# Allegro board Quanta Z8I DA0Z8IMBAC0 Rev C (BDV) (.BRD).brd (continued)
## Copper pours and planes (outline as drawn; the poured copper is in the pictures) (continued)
+USBPWRD2 on BOTTOM (solid shape): 229.19,125.3 229.19,124.81 227.9,124.81 227.9,124.61 229.19,124.61 229.19,124.31 227.9,124.31 227.9,124.11 229.19,124.11 229.19,123.81 227.9,123.81 227.9,123.61 229.19,123.61 229.19,123.34 229.17,123.31 226.75,123.31 226.61,123.45 226.61,125.11 226.82,125.31 229.18,125.31
+USBPWRD2 on BOTTOM (solid shape): 221.12,106.73 221.12,105.23 221,105.12 220.6,105.12 220.39,104.92 220.39,104.05 220.03,103.69 220,103.69 219.78,103.63 219.63,103.47 219.62,103.44 218.15,103.44 217.86,103.73 217.86,105.26 218.01,105.41 218.01,106.76 218.06,106.81 221.04,106.81
+USBPWRD2 on BOTTOM (solid shape): 212.45,114.58 212.45,111.99 211.89,111.43 210.52,111.43 210.3,111.65 210.3,112.88 211.8,112.88 211.8,113.71 211.6,113.71 211.6,112.88 211.3,112.88 211.3,113.71 211.1,113.71 211.1,112.88 210.8,112.88 210.8,113.71 210.6,113.71 210.6,112.88 210.3,112.88 210.3,114.51 210.62,114.83 212.2,114.83
+USBPWRD2 on IN3 (solid shape): outline of 1535 points within 210.32,103.49 230.23,125.45
+VAC_IN on TOP (solid shape): 14.02,198.93 14.02,196.6 14.5,196.13 14.99,196.13 15.23,195.89 15.23,193.9 14.84,193.51 13.27,193.51 11.51,195.28 11.51,197.28 10.67,198.12 9.68,198.12 9.22,198.57 9.22,199.64 9.86,200.28 12.68,200.28
+VAC_IN on TOP (solid shape): 57.13,201.8 57.13,200.73 57.33,200.53 61.01,200.53 61.22,200.33 61.22,197.46 61.15,197.34 61.13,197.2 61.13,197.13 61.15,197.05 61.17,197.02 59.67,195.53 56.72,195.53 56.5,195.75 56.5,196.06 56.49,196.1 56.49,197.2 55.82,197.88 55.82,198.56 55.96,198.7 55.96,201.95 56.09,202.08 56.85,202.08
+VAC_IN on SVCC (solid shape): outline of 96 points within 7.27,190.04 62.28,210.67
+VAC_IN on IN2 (solid shape): outline of 971 points within 9.58,191.08 62.24,202.25
+VAC_IN on IN4 (solid shape): outline of 961 points within 9.4,191.11 62.28,201.99
+VGPU_CORE on TOP (solid shape): 130.03,191.42 130.29,191.15 130.3,191.15 130.38,191.05 130.51,191.01 130.61,191.01 130.69,190.97 130.71,190.89 130.71,190.85 130.78,190.64 130.97,190.51 130.98,190.51 131.11,190.37 131.11,190.29 131.1,190.26 131.06,190.24 131,190.18 131,190.07 130.89,189.96 130.41,189.96 129.61,190.76 129.6,190.8 129.61,190.83 129.81,191.03 129.81,191.03 129.91,191.11 129.94,191.24 129.94,191.38 129.96,191.41 129.99,191.43
+VGPU_CORE on TOP (solid shape): 113.41,215.97 113.44,215.9 113.4,215.82 112.3,214.4 111.9,212.65 112.61,210.34 114.5,208.83 114.5,204.74 113.89,204.13 113.87,204.13 113.68,204.04 113.55,203.86 113.53,203.83 112.08,203.83 111.77,203.52 111.77,202.52 111.95,202.34 112.13,202.34 112.37,202.1 112.37,200.99 112.26,200.89 108.72,200.89 106.83,202.78 106.8,202.78 106.75,202.82 106.68,202.83 105.99,202.83 105.57,203.26 105.57,204.13 106.39,204.95 106.39,206.93 104.31,209.01 104.31,210.94 106.39,213.02 106.39,213.31 109.91,216.84 110.22,216.84 110.52,217.14 112.24,217.14
+VGPU_CORE on TOP (solid shape): outline of 2141 points within 124.36,190.24 136.43,209.57
+VGPU_CORE on BOTTOM (solid shape): 112.45,216.79 112.45,214.69 112.44,214.68 112.04,213.7 111.9,212.65 112.04,211.6 112.44,210.62 112.45,210.61 112.45,210.21 113.29,209.37 113.29,206.35 113.66,205.98 113.98,205.98 114.21,205.75 114.21,204.84 113.29,203.92 113.29,201.57 112.42,200.71 108.51,200.71 107.7,201.52 107.7,208.02 105.54,210.18 105.54,210.41 109.85,214.72 109.85,214.85 109.85,214.86 109.85,215.22 109.85,215.23 109.85,216.34 110.66,217.16 112.08,217.16
+VGPU_CORE on BOTTOM (solid shape): outline of 623 points within 129.9,204.36 141.58,217.42
+VGPU_CORE on SVCC (solid shape): 140.15,217.47 140.06,217.34 140.03,217.2 140.1,216.99 140.26,216.85 140.26,209.14 140.18,209.02 140.15,208.87 140.18,208.73 140.26,208.6 140.26,206.88 135.76,202.39 135.71,202.3 135.69,202.21 135.69,202.13 135.58,202.01 135.54,201.85 135.58,201.69 135.69,201.56 135.69,199.6 135.59,199.48 135.56,199.33 135.59,199.18 135.69,199.05 135.69,192.93 135.59,192.81 135.56,192.65 135.59,192.5 135.69,192.38 135.69,188.85 134.57,187.73 133.18,187.73 133.05,187.91 132.84,187.98 132.63,187.91 132.5,187.73 126.4,187.73 123.81,190.31 123.72,190.5 123.53,190.6 116.86,197.27 116.88,197.35 116.89,197.44 116.78,197.71 116.51,197.82 116.43,197.81 116.35,197.78 115.8,198.32 115.72,198.38 115.62,198.4 110.9,198.4 104.45,204.85 104.45,211.37 110.54,217.47
+VGPU_CORE on IN2 (solid shape): outline of 6717 points within 104.58,188.21 140.15,217.44
+VGPU_CORE on IN3 (solid shape): outline of 2725 points within 124.54,190.11 134.86,206.8
+VGPU_CORE on IN4 (solid shape): outline of 4682 points within 125.22,189.04 143.94,217.47
ADOGND on TOP (solid shape): outline of 506 points within 10.57,24.72 23.58,38.56
ADOGND on TOP (solid shape): outline of 644 points within 1.01,14.81 23.45,29.83
ADOGND on BOTTOM (solid shape): 13.08,24.83 13.08,24.58 13.13,24.53 13.13,19.7 13.6,19.23 13.61,17.2 11.85,16.19 10.33,16.19 10.24,16.25 10.26,16.36 10.44,16.61 10.5,16.91 10.5,16.99 10.48,17.08 10.5,17.16 10.58,17.2 11.67,17.2 12.63,17.96 12.16,19.08 12.16,23.44 12.62,24.57 11.65,25.32 10.64,25.32 10.64,25.64 12.26,25.64
ADOGND on BOTTOM (solid shape): outline of 132 points within 12.73,14.81 23.53,28.42
ADOGND on SGND (solid shape): outline of 116 points within 1.01,14.35 23.55,38.58
ADOGND on IN1 (solid shape): 5.49,29.64 5.51,29.45 5.52,29.25 5.52,27.65 5.51,27.44 5.48,27.24 5.58,27.14 11.88,27.14 13.23,25.79 13.87,24.41 13.37,22.98 13.37,19.54 13.81,18.71 13.83,17.78 12.65,16.6 12.14,16.6 11.72,16.19 10.33,16.19 10.24,16.25 10.26,16.36 10.44,16.61 10.5,16.91 10.5,16.99 10.48,17.08 10.5,17.16 10.58,17.2 11.67,17.2 12.63,17.96 12.16,19.08 12.16,23.44 12.62,24.57 11.65,25.32 10.18,25.32 10.1,25.36 10.08,25.44 10.1,25.53 10.1,25.61 10.04,25.91 9.86,26.16 9.66,26.36 6,26.36 5.69,26.06 5.62,26.03 5.55,26.05 5.37,26.17 5.15,26.21 4.39,26.21 3.97,26.03 3.79,25.61 3.8,25.53 3.81,25.45 3.8,25.36 3.72,25.32 2.67,25.32 2.73,25.46 2.75,25.61 2.57,26.03 2.15,26.21 1.39,26.21 1.19,26.17 1.01,26.07 1.01,26.64 3.5,26.64 4.21,26.94 4.51,27.65 4.51,29.25 4.5,29.38 4.47,29.52 4.49,29.6 4.57,29.64
ADOGND on SVCC (solid shape): outline of 111 points within 3.43,14.35 23.55,38.58
ADOGND on IN2 (solid shape): outline of 1139 points within 1.01,14.96 23.53,38.56
ADOGND on IN3 (solid shape): 5.49,29.64 5.51,29.45 5.52,29.25 5.52,27.65 5.51,27.44 5.48,27.24 5.58,27.14 11.88,27.14 13.23,25.79 13.87,24.41 13.37,22.98 13.37,19.54 13.75,18.91 13.87,18.19 13.3,17.61 13.08,17.61 13.07,17.62 12.81,17.62 12.59,17.84 12.6,18.54 12.16,19.08 12.16,23.44 12.62,24.57 11.65,25.32 10.18,25.32 10.1,25.36 10.08,25.44 10.1,25.53 10.1,25.61 10.04,25.91 9.86,26.16 9.66,26.36 6.25,26.36 5.92,26.03 5.61,26.03 5.4,26.18 5.15,26.23 4.39,26.23 3.95,26.05 3.77,25.61 3.78,25.48 3.82,25.35 3.84,25.32 2.7,25.32 2.76,25.46 2.77,25.61 2.59,26.05 2.15,26.23 1.39,26.23 1.19,26.2 1.01,26.1 1.01,26.64 3.5,26.64 4.21,26.94 4.51,27.65 4.51,29.25 4.5,29.38 4.47,29.52 4.49,29.6 4.57,29.64
ADOGND on SGND1 (solid shape): outline of 115 points within 1.01,14.35 23.55,38.58
ADOGND on IN4 (solid shape): outline of 1031 points within 1.01,14.81 23.53,38.56
ADOGND on SGND2 (solid shape): outline of 118 points within 1.01,14.35 23.55,38.58
BAT-V on TOP (solid shape): outline of 1888 points within 101.4,94.54 138.48,117.01
BAT-V on BOTTOM (solid shape): 138.61,114.93 138.61,113.89 139.47,113.03 139.47,112.4 138.85,112.4 138.31,112.95 135.23,112.95 134.74,113.45 134.74,114.11 135.56,114.93 135.56,115.67 135.82,115.92 137.62,115.92
BAT-V on BOTTOM (solid shape): 101.95,105.55 101.95,104.67 102.59,104.02 102.59,102.29 102.77,102.12 103.93,102.12 104.06,101.99 104.06,100.69 103.58,100.22 100.57,100.22 100.1,100.68 100.1,101.62 99.39,102.33 99.39,104.36 100.01,104.97 100.16,105.13 100.16,105.71 100.26,105.81 101.69,105.81
CRT_VCC_R on TOP (solid shape): 17.79,150.05 17.79,149.13 17.7,149.04 16.8,149.04 16.33,148.57 13.64,148.57 13.58,148.64 13.58,149.41 14.39,150.22 17.62,150.22
CRT_VCC_R on TOP (solid shape): 26.89,157.94 26.89,156.52 27.28,156.13 27.69,156.13 28.62,155.2 28.62,153.98 27.8,153.98 27.64,154.13 27.64,154.89 26.32,156.21 25.92,156.21 25.82,156.31 25.82,157.12 25.42,157.52 25.42,158.33 25.56,158.46 26.37,158.46
CRT_VCC_R on BOTTOM (solid shape): 11.01,159.98 11.01,158.08 10.92,157.99 10.92,157.63 10.74,157.46 9.31,157.46 8.32,158.44 6.04,158.44 5.86,158.63 5.86,159.23 6.09,159.46 6.16,159.46 6.2,159.45 6.28,159.43 6.36,159.41 6.44,159.41 6.52,159.42 6.59,159.44 6.63,159.46 6.73,159.36 8.36,159.36 8.54,159.53 9.2,159.53 9.2,159.48 9.21,159.42 9.23,159.37 9.26,159.32 9.29,159.27 9.33,159.23 9.38,159.2 9.43,159.17 9.48,159.15 9.53,159.13 9.59,159.13 9.65,159.13 9.7,159.14 9.76,159.16 9.81,159.18 9.86,159.21 9.9,159.25 9.93,159.29 9.96,159.34 9.99,159.39 10,159.45 10.01,159.51 10.01,159.56 10,159.62 9.99,159.67 9.96,159.73 9.93,159.77 9.9,159.82 9.86,159.86 9.81,159.89 9.76,159.91 9.7,159.93 9.65,159.94 9.59,159.94 9.53,159.94 9.48,159.92 9.43,159.9 9.38,159.87 9.33,159.84 9.29,159.8 9.26,159.75 9.23,159.7 9.21,159.65 9.2,159.59 9.2,159.53 8.54,159.53 9.28,160.27 10.72,160.27
CRT_VCC_R on IN1 (solid shape): 15.61,150.11 16.74,150.11 17.09,149.76 17.09,148.92 16.82,148.64 15.62,148.64 15.61,148.63 14.31,148.63 14.13,148.81 14.13,149.08 14.14,149.09 14.14,149.72 14.66,150.24 15.48,150.24
CRT_VCC_R on IN1 (solid shape): 26.74,157.98 26.74,157.64 26.78,157.43 26.9,157.25 27.16,156.99 27.16,155.98 26.93,155.75 26.04,155.75 25.84,155.95 25.84,158.11 26.61,158.11
CRT_VCC_R on IN1 (solid shape): 10.85,158.09 10.85,157.41 10.94,157.32 10.97,157.24 10.94,157.17 10.86,157.06 10.83,156.92 10.92,156.68 11.19,156.54 11.2,156.51 11.2,155.71 11.1,155.61 9.16,155.61 8.97,155.8 8.94,155.88 8.99,155.96 9.11,156.09 9.15,156.26 9.05,156.51 8.8,156.62 8.76,156.63 8.74,156.67 8.74,158.14 8.94,158.34 10.6,158.34
EN_SA on TOP (solid shape): 167.31,130.71 167.25,130.64 167.25,129.36 167.21,129.32 166.84,129.32 166.37,129.79 166.37,131.01 167.31,131.01
FBA_VREFC_1 on BOTTOM (solid shape): 159.35,186.87 159.35,186.45 159.41,186.39 159.41,185.92 159.29,185.79 159.16,185.61 159.12,185.39 159.12,184.45 159.13,184.35 159.13,184.02 159.02,183.91 159.02,183.1 158.99,183.06 158.84,183.06 158.75,183.15 158.75,183.56 158.51,183.8 158.51,185.93 158.76,186.18 158.84,186.28 158.9,186.39 158.97,186.45 158.97,186.89 159.03,186.91 159.3,186.91
G5335-AGND-2 on TOP (solid shape): 169.71,157.13 169.71,155.82 169.67,155.72 169.65,155.61 169.66,155.51 169.7,155.42 169.71,155.39 169.67,155.35 169.67,153.66 169.61,153.6 169.61,152.79 168.3,152.79 168.11,152.97 168.11,153.39 167.91,153.59 167.91,153.88 168.02,154 168.27,154 168.34,153.98 168.4,153.98 168.66,154.07 168.8,154.31 168.8,154.33 168.81,154.34 168.81,156.91 169.19,157.29 169.55,157.29 169.55,157.29
G5335-AGND-2 on BOTTOM (solid shape): 168.71,153.46 168.71,152.86 168.63,152.78 168.26,152.78 168.19,152.85 168.19,153.24 168.18,153.29 168.17,153.37 168.14,153.39 168.11,153.43 167.68,153.86 167.64,153.9 167.5,154.03 167.42,154.03 167.42,154.04 166.63,154.04 166.63,154.29 167.42,154.29 167.42,154.29 167.66,154.29 167.66,154.29 167.88,154.29
G5335-LX-1 on BOTTOM (solid shape): 140.16,128.29 140.77,128.29 141.28,127.78 142.8,127.78 142.8,126.9 142.92,126.78 143.58,126.78 143.67,126.69 143.67,124.15 143.31,123.8 143.31,122.59 143.7,122.2 143.7,121.57 143.54,121.41 142.73,121.41 142.37,121.76 142.37,123 143.06,123 143.06,123.79 142.82,123.79 142.82,123 142.37,123 142.37,123.85 142.43,123.9 142.46,123.92 142.5,123.97 142.5,125.9 142.4,126.01 142.34,126.01 142.34,126.02 141.55,126.02 141.55,126.01 140.19,126.01 139.78,125.6 139.75,125.58 139.69,125.55 139.64,125.5 139.6,125.45 139.56,125.4 139.55,125.37 139.35,125.17 135.54,125.17 135.53,125.16 135.33,125.35 135.33,126.27 142.34,126.27 142.34,126.52 141.55,126.52 141.55,126.27 135.33,126.27 135.33,127.01 135.36,127.03 135.4,127.07 135.43,127.11 135.46,127.16 135.48,127.21 135.49,127.26 135.5,127.31 135.5,127.38 135.49,127.45 135.47,127.51 135.72,127.76 138.66,127.76 139.53,128.62 139.83,128.62
G5335-LX-2 on BOTTOM (solid shape): 164.5,160.64 164.5,159.6 163.77,158.86 163.77,157.79 163.46,157.48 163.46,157.1 163.74,156.82 163.89,156.82 163.9,156.8 163.9,156.02 163.9,155.81 164,155.71 164.63,155.71 164.63,153.16 164.4,152.93 164.4,152.03 164.15,152.03 164.15,152.81 163.9,152.81 163.9,152.03 163.65,152.03 163.65,153.04 163.72,153.11 163.72,154.75 163.44,155.04 162.65,155.04 162.4,155.29 163.42,155.29 163.42,155.54 162.63,155.54 162.63,155.29 162.4,155.29 159.62,158.07 159.62,158.09 158.86,158.85 158.84,158.85 158.28,159.41 158.28,160.65 158.68,161.05 164.1,161.05
G5719LX1.5V on BOTTOM (solid shape): 9.91,34.95 9.91,34.09 9.83,34.01 9.45,34.01 9.15,33.71 8.55,33.1 6.13,33.1 6.06,33.17 6.06,33.92 6.13,33.99 7.38,33.99 7.61,34.22 7.61,34.75 7.91,35.05 9.81,35.05
L_SPK+ on TOP (solid shape): 40.53,94.09 40.53,93.23 40.48,93.17 40.47,93.17 40.28,92.99 39.91,92.99 39.72,93.17 38.69,93.17 38.52,93.35 38.52,94.08 38.61,94.18 40.44,94.18
L_SPK+ on BOTTOM (solid shape): 19.55,37.63 19.55,36.74 19.51,36.7 19.51,35.01 19.51,35.01 19.32,35.01 19.31,35.02 19.31,36.49 19.06,36.74 19.06,37.64 19.17,37.75 19.43,37.75
L_SPK+ on IN4 (solid shape): 19.89,40.34 19.89,38.26 19.58,37.95 19.58,36.75 19.43,36.59 19.11,36.59 19.02,36.69 19.02,37.85 18.38,38.48 18.38,40.48 18.94,41.03 19.19,41.03
L_SPK+ on IN4 (solid shape): 39.35,94.69 39.48,94.52 39.68,94.45 39.7,94.45 39.85,94.48 39.98,94.58 40.04,94.59 40.09,94.56 40.21,94.48 40.34,94.45 40.42,94.45 40.47,94.47 40.55,94.44 40.58,94.37 40.58,93.77 40.44,93.64 37.98,93.64 37.92,93.69 37.92,94.67 37.99,94.73 39.33,94.73
L_SPK+_1 on TOP (solid shape): 38.37,92.87 39.51,92.87 39.64,92.74 39.64,91.78 39.6,91.74 37.85,91.74 37.17,92.42 37.17,93.07 37.25,93.15 38.09,93.15
L_SPK+_1 on TOP (solid shape): 42.42,101.57 42.42,100.68 42.31,100.58 42.31,100.05 42.21,99.94 41.41,99.94 41.28,100.08 41.28,101.36 41.14,101.49 41.14,101.76 41.32,101.94 42.05,101.94
L_SPK+_1 on BOTTOM (solid shape): 82.02,198.7 82.02,196.41 81.87,196.26 81,196.26 80.85,196.41 80.85,198.7 81.05,198.9 81.82,198.9
L_SPK+_1 on IN4 (solid shape): 82.02,197.51 82.02,196.41 81.87,196.26 81,196.26 80.85,196.41 80.85,197.63 80.98,197.76 81.77,197.76
L_SPK+_1 on IN4 (solid shape): 42.29,102.16 42.29,101.62 42.22,101.54 41.2,101.54 41.16,101.58 41.16,101.86 41.12,101.91 40.43,102.59 40.43,102.75 40.89,103.21 41.24,103.21
L_SPK+_2 on TOP (solid shape): 41.58,96.38 41.58,96.02 41.46,95.91 41.22,95.91 40.58,95.27 40.58,94.64 40.5,94.56 38.58,94.56 38.57,94.57 38.57,95.3 38.88,95.61 40.11,95.61 40.97,96.47 41.49,96.47
L_SPK+_2 on BOTTOM (solid shape): 39.49,98.48 39.49,96.62 40.58,95.53 40.58,94.67 40.46,94.56 39.31,94.56 38.62,95.25 38.62,96.52 38.72,96.62 38.72,98.45 38.77,98.5 39.47,98.5
L_SPK- on TOP (solid shape): 42.86,94.05 42.86,93.27 42.77,93.19 40.95,93.19 40.84,93.31 40.84,94.15 40.87,94.18 42.73,94.18
L_SPK- on BOTTOM (solid shape): 20.96,40.12 20.96,38.38 20.3,37.71 20.27,37.69 20.24,37.66 20.17,37.58 20.17,37.49 20.17,37.38 20.17,36.47 19.91,36.21 19.91,35.02 19.91,35.01 19.74,35.01 19.71,35.04 19.71,36 19.71,36.32 19.64,36.39 19.64,36.68 19.66,36.7 19.66,36.78 19.66,36.85 19.66,36.92 19.66,37.44 19.66,37.51 19.66,37.58 19.66,37.89 20.03,38.26 20.03,38.89 19.42,39.5 19.42,40.05 19.66,40.29 20.79,40.29
L_SPK- on IN4 (solid shape): 21.88,40.69 21.88,39.99 20.86,38.98 20.65,38.98 20.29,39.33 20.29,40.25 21.05,41 21.57,41
L_SPK- on IN4 (solid shape): 42.78,94.07 42.78,93.11 42.01,92.34 41.57,92.34 40.9,93.02 40.9,93.6 40.91,93.61 40.91,94.1 40.95,94.15 42.71,94.15
L_SPK-_1 on TOP (solid shape): 42.4,92.6 42.4,91.9 40.91,90.41 39.75,90.41 39.66,90.5 39.66,91.32 41.09,92.75 42.26,92.75
L_SPK-_1 on TOP (solid shape): 40.82,101.83 40.82,101.38 40.97,101.23 40.97,100.5 40.97,100.44 40.96,100.38 40.96,99.71 40.92,99.66 40,99.66 39.94,99.72 39.94,100.96 39.69,101.22 39.69,101.61 39.7,101.66 39.7,101.7 39.7,101.91 39.77,101.97 40.67,101.97
L_SPK-_1 on BOTTOM (solid shape): 83.52,198.75 83.52,196.47 83.37,196.31 82.5,196.31 82.35,196.47 82.35,198.75 82.55,198.95 83.32,198.95
L_SPK-_1 on IN4 (solid shape): 83.52,197.76 83.52,196.47 83.37,196.31 82.5,196.31 82.35,196.47 82.35,198.07 82.43,198.14 83.14,198.14
L_SPK-_1 on IN4 (solid shape): 40.05,102.54 40.49,102.1 40.81,101.78 40.81,101.63 40.73,101.54 39.51,101.54 38.58,102.47 38.58,102.63 39.24,103.29 39.3,103.29
L_SPK-_2 on TOP (solid shape): 43.26,95.95 43.26,95.42 42.88,95.03 42.88,94.62 42.82,94.56 40.82,94.56 40.76,94.63 40.76,94.76 40.77,94.8 40.76,94.84 40.75,94.9 41.35,95.49 42.2,95.49 42.72,96.01 43.2,96.01
L_SPK-_2 on BOTTOM (solid shape): 40.75,98.47 40.75,96.61 40.86,96.5 41.05,96.5 42.17,95.38 42.63,95.38 42.88,95.13 42.88,94.68 42.73,94.52 40.91,94.52 40.77,94.67 40.77,95.56 39.97,96.36 39.97,98.48 40,98.52 40.7,98.52
LGATE1_CORE on BOTTOM (solid shape): 149.84,156.56 149.84,156.13 149.99,155.98 150.96,155.98 150.96,155.37 149.3,155.37 149.3,156.56 149.41,156.66 149.74,156.66
MUX_3V on TOP (solid shape): 33.08,131.31 33.08,130.89 33.28,130.69 34.2,130.69 34.4,130.49 34.4,128.88 34.33,128.81 33.34,128.81 33.23,128.7 32.68,128.7 32.53,128.84 30.85,128.84 30.78,128.85 29.12,128.85 28.78,128.51 28.01,128.51 27.92,128.6 27.92,128.8 28.53,129.41 31.51,129.41 31.85,129.75 32.38,129.75 32.58,129.95 32.58,131.32 32.64,131.38 33.02,131.38
MUX_3V on BOTTOM (solid shape): outline of 1000 points within 19.27,119.04 34.64,133.82
Net_88 on TOP (solid shape): 8.44,48.63 4.63,48.63 4.59,48.68 4.59,51.23 8.44,51.23
Net_88 on BOTTOM (solid shape): 8.44,51.22 8.44,48.83 8.25,48.63 4.63,48.63 4.59,48.68 4.59,51.23 8.43,51.23
Net_88 on IN1 (solid shape): 8.44,48.63 4.63,48.63 4.59,48.68 4.59,51.23 8.44,51.23
Net_88 on IN2 (solid shape): 8.44,48.63 4.63,48.63 4.59,48.68 4.59,51.23 8.44,51.23
Net_88 on IN3 (solid shape): 8.44,48.63 4.63,48.63 4.59,48.68 4.59,51.23 8.44,51.23
Net_88 on IN4 (solid shape): 8.45,48.63 4.63,48.63 4.59,48.68 4.59,51.23 8.45,51.23
PHASE1_CORE on BOTTOM (solid shape): 148.69,156.36 148.69,155.24 148.91,155.03 149.22,155.03 149.23,155.01 149.66,155.01 149.7,154.97 149.7,154.97 149.98,154.68 149.98,151.59 149.97,151.58 146.87,151.58 146.69,151.76 146.69,154.32 146.8,154.32 146.9,154.37 146.95,154.48 146.95,154.86 146.9,154.97 146.8,155.01 146.69,155.01 146.69,156.38 146.89,156.59 148.47,156.59
PHASE2_CORE on BOTTOM (solid shape): 157,144.78 157,144.37 156.72,144.09 156.2,144.09 156.19,144.1 155.25,144.1 155.25,144.4 156.21,144.4 156.37,144.55 156.37,144.8 156.52,144.95 156.82,144.95
PHASE2_CORE on BOTTOM (solid shape): 151.64,139.52 151.64,136.09 151.36,135.81 149.62,135.81 149.61,135.81 149.35,135.55 149.34,135.55 149.22,135.46 149.14,135.34 149.13,135.33 149,135.2 148.54,135.2 148.34,135.4 148.34,137.53 148.37,137.55 148.44,137.6 148.46,137.69 148.46,138.07 148.44,138.15 148.37,138.21 148.34,138.22 148.34,139.7 151.46,139.7
PHASE_GT on BOTTOM (solid shape): 153.19,165.7 154.13,165.7 154.13,165.4 153.17,165.4 153.01,165.25 153.01,164.97 152.86,164.82 152.62,164.82 152.47,164.97 152.47,165.32 152.86,165.71 153.19,165.71
PHASE_GT on BOTTOM (solid shape): 141.28,167.15 141.28,166.39 141.68,165.99 142.37,165.99 142.47,165.88 142.47,162.76 142,162.76 140.09,160.85 139.18,160.85 139.17,160.85 139.17,165.03 139.2,165.05 139.26,165.1 139.29,165.19 139.29,165.57 139.26,165.65 139.2,165.71 139.17,165.72 139.17,167.08 139.5,167.41 141.02,167.41
PHASE_SA on TOP (solid shape): 168.49,130.57 169.41,130.57 169.47,130.5 169.47,129.92 169.35,129.79 168.3,129.79 167.52,130.58 167.52,131.04 167.34,131.21 166.37,131.21 166.37,131.51 167.3,131.51 167.3,131.52 167.54,131.52
PHASE_SA on BOTTOM (solid shape): 159.1,131.52 159.08,131.49 159.03,131.38 159.01,131.26 159.13,130.98 159.42,130.86 159.54,130.87 159.64,130.92 159.68,130.95 159.77,130.86 159.77,128.52 160.05,128.24 162.51,128.24 162.74,128.47 163.02,128.47 163.17,128.32 163.17,128.06 163.42,127.82 164.02,127.82 164.13,127.71 164.13,126.04 163.97,125.87 157.27,125.87 157,126.14 157,128.54 157.01,128.55 157.04,128.6 157.04,128.65 157.04,129.03 157.04,129.08 157.01,129.12 157,129.13 157,129.36 156.62,129.74 156.62,131.72 156.82,131.92 158.7,131.92
PVADPTR on TOP (solid shape): 41.68,117.56 41.68,116.09 42.23,115.55 42.23,114.17 42.13,114.07 38.91,114.07 38.79,114.2 38.79,115.47 38.54,115.71 38.54,117.63 38.7,117.79 39.13,117.79 39.13,117.79 41.44,117.79
PVADPTR on TOP (solid shape): outline of 219 points within 60.05,190.85 68.05,200.53
R_SPK+ on TOP (solid shape): 48.79,94.37 48.79,93.52 48.65,93.38 47.81,93.38 47.51,93.09 47.05,93.09 46.69,93.44 46.69,94.24 46.92,94.46 48.7,94.46
R_SPK+ on BOTTOM (solid shape): 21.41,37.72 21.41,36.81 20.71,36.11 20.71,35.02 20.7,35.01 20.54,35.01 20.51,35.04 20.51,36 20.51,36.19 20.91,36.59 20.91,36.75 20.91,36.79 20.91,37.73 21.05,37.86 21.27,37.86
R_SPK+ on IN4 (solid shape): 47.81,94.16 47.81,92.83 47.6,92.62 46.75,92.62 46.56,92.81 46.56,94.12 46.75,94.3 47.66,94.3
R_SPK+ on IN4 (solid shape): 22.28,37.9 22.41,37.89 22.54,37.89 22.64,37.79 22.64,36.83 22.2,36.38 21.08,36.38 20.9,36.56 20.9,37.65 21.18,37.93 22.14,37.93
R_SPK+_1 on TOP (solid shape): 50.21,94.53 50.21,92.51 49.62,91.92 47.92,91.92 47.9,91.94 47.9,92.93 48.02,93.05 49.02,93.05 49.19,93.22 49.19,94.11 49.19,94.11 49.19,94.65 49.32,94.78 49.97,94.78
R_SPK+_1 on TOP (solid shape): 42.07,106.94 42.13,106.8 42.22,106.68 42.49,106.42 42.49,105.83 42.24,105.58 42.24,105.32 42.22,105.3 42.22,105.12 42.21,105.12 42.21,104.6 42.2,104.59 41.27,104.59 41.23,104.63 41.23,106.58 41.62,106.97 42.06,106.97
R_SPK+_1 on BOTTOM (solid shape): 87.99,198.75 87.99,196.47 87.84,196.31 86.97,196.31 86.82,196.47 86.82,198.75 87.02,198.95 87.79,198.95
R_SPK+_1 on IN3 (solid shape): 42.45,106.69 42.45,106.34 42.24,106.13 41.45,106.13 40.43,107.15 40.43,107.61 40.9,108.08 41.06,108.08
R_SPK+_1 on IN3 (solid shape): 88.01,196.82 88.01,195.42 86.8,194.21 86.41,194.21 86.03,194.59 86.03,195.04 86.8,195.81 86.8,196.75 86.97,196.92 87.91,196.92
R_SPK+_2 on TOP (solid shape): 48.77,95.83 48.77,94.89 48.72,94.84 47.06,94.84 45.64,96.26 45.64,96.95 46.18,97.49 47.11,97.49
R_SPK+_2 on BOTTOM (solid shape): 44.17,97.83 46.83,97.83 47.18,97.48 47.18,96.73 47.01,96.56 43.68,96.56 43.62,96.62 42.59,96.62 42.48,96.73 42.48,98.46 42.55,98.53 43.47,98.53
R_SPK- on TOP (solid shape): 45.25,94.14 45.25,93.28 45.2,93.23 44.17,93.23 43.91,92.96 43.34,92.96 43.16,93.14 43.16,94.16 45.23,94.16
R_SPK- on BOTTOM (solid shape): 20.78,37.59 20.78,36.63 20.31,36.17 20.31,35.01 20.13,35.01 20.11,35.03 20.11,36 20.11,36.25 20.3,36.44 20.3,37.55 20.42,37.67 20.69,37.67
R_SPK- on IN4 (solid shape): 44.24,94.02 44.24,92.53 43.82,92.11 43.5,92.11 43.11,92.5 43.11,94.05 43.24,94.18 44.09,94.18
R_SPK- on IN4 (solid shape): 22.54,38.99 22.54,38.18 22.26,38.18 22.05,38.15 21.85,38.06 21.17,38.06 21.06,37.96 21.05,37.95 20.91,37.87 20.82,37.72 20.82,37.71 20.8,37.69 20.8,36.6 20.68,36.47 20.4,36.47 20.26,36.61 20.26,37.91 21.45,39.09 22.44,39.09
R_SPK-_1 on TOP (solid shape): 46.57,91.51 46.57,90.54 46.51,90.48 45.51,90.48 44.33,91.67 44.33,92.69 44.44,92.8 45.28,92.8
R_SPK-_1 on TOP (solid shape): 43.2,105.56 43.28,105.56 43.45,105.56 43.71,105.29 43.71,103.76 43.59,103.64 42.69,103.64 42.53,103.8 42.53,105.17 42.93,105.58 43.12,105.58
R_SPK-_1 on BOTTOM (solid shape): 86.52,198.75 86.52,196.47 86.36,196.31 85.5,196.31 85.35,196.47 85.35,198.75 85.55,198.95 86.31,198.95
R_SPK-_1 on IN3 (solid shape): 43.57,105.47 43.57,105.27 42.92,104.62 41.35,104.62 41.29,104.68 41.29,105.56 41.4,105.67 43.37,105.67
R_SPK-_1 on IN3 (solid shape): 86.49,196.82 86.49,195.93 85.27,194.71 84.89,194.71 84.51,195.09 84.51,195.48 85.32,196.29 85.32,196.85 85.4,196.92 86.39,196.92
R_SPK-_2 on TOP (solid shape): 44.28,96.4 44.28,96.08 44.91,95.45 45.9,95.45 46.13,95.22 46.13,94.79 45.88,94.54 43.15,94.54 43.09,94.6 43.09,94.98 43.64,95.54 43.64,96.29 43.8,96.46 44.23,96.46
R_SPK-_2 on BOTTOM (solid shape): 41.99,98.45 41.99,96.64 42.17,96.46 43.55,96.46 44.18,95.83 44.18,94.67 44.06,94.55 43.2,94.55 43.05,94.69 43.05,95.37 42.89,95.54 42.24,95.54 41.22,96.56 41.22,98.47 41.26,98.52 41.93,98.52
RING2 on TOP (solid shape): 20.86,27.91 20.86,25.75 20.32,25.22 19.66,25.22 19.64,25.24 19.64,25.52 20.09,25.98 20.09,27.86 20.25,28.01 20.76,28.01
RING2 on BOTTOM (solid shape): 6.84,29.79 6.84,28.31 7.21,27.94 7.21,27.72 7.01,27.52 5.79,27.52 4.58,26.31 4.48,26.31 4.43,26.26 4.39,26.26 3.93,26.07 3.74,25.61 3.74,25.55 3.75,25.48 3.65,25.38 1.4,25.38 1.26,25.52 1.26,26.43 1.32,26.49 3.81,26.49 5.88,28.56 5.88,29.7 6.02,29.83 6.79,29.83
RING2 on IN4 (solid shape): 8.16,27.5 8.16,26.72 8.09,26.65 6.77,26.65 6.08,27.33 6.08,27.99 6.17,28.09 7.58,28.09
RING2 on IN4 (solid shape): 20.96,27.77 20.96,27.1 21.4,26.65 21.4,26.05 21.25,25.91 20.5,25.91 20.23,26.18 20.23,26.84 20.2,26.87 20.2,27.85 20.29,27.93 20.79,27.93
SLEEVE on TOP (solid shape): 19.94,27.86 19.94,26.13 19.46,25.65 19.46,25.32 19.36,25.22 18.93,25.22 18.9,25.24 18.9,27.66 19.31,28.06 19.74,28.06
SLEEVE on TOP (solid shape): 4.01,16.85 5.87,14.99 5.87,14.49 5.79,14.4 3.82,14.4 3.71,14.51 3.71,15.6 3.4,15.92 3.07,15.92 2.18,16.8 2.18,17.2 4.01,17.2
SLEEVE on IN3 (solid shape): 19.89,27.7 19.89,25.68 19.46,25.25 18.61,25.25 18.44,25.41 18.44,27.79 18.66,28.01 19.59,28.01
SLEEVE on IN3 (solid shape): 6.06,15.56 6.06,14.58 5.94,14.47 4.48,14.47 4.48,14.46 3.84,14.46 3.76,14.55 3.76,15.56 3.89,15.7 5.92,15.7
TYPEC1_USB0 on TOP (solid shape): 11.56,70.43 11.56,69.58 11.39,69.42 11.39,68.69 10.97,68.26 10.66,68.26 10.6,68.33 10.6,68.6 10.53,68.67 10.53,68.69 10.24,68.97 10.24,69.73 11,70.49 11.5,70.49
TYPEC1_USB0 on TOP (solid shape): 11.1,64.94 11.1,64.35 11.31,64.14 12.18,64.14 12.32,64 12.32,63 11.95,62.63 10.82,62.63 10.21,63.24 10.21,63.78 10.65,64.21 10.65,64.97 10.71,65.03 11.01,65.03
TYPEC1_USB0 on TOP (solid shape): 35.56,107.58 35.56,104.55 35.41,104.4 35.33,104.4 35.22,104.51 34.22,104.51 34.1,104.57 33.98,104.59 33.85,104.57 33.73,104.51 33.59,104.51 32.95,103.87 32.95,102.85 32.49,102.39 32.49,102.34 32.31,102.16 32.31,101.85 32.49,101.67 32.49,101.47 32.63,101.33 33.54,101.33 33.74,101.13 33.74,100.46 33.79,100.36 33.9,100.31 34.46,100.31 34.56,100.36 34.61,100.46 34.61,100.87 34.65,100.96 34.74,100.97 34.81,100.95 34.87,100.95 35.16,101.07 35.28,101.35 35.28,101.4 35.92,101.4 36.04,101.28 36.04,101.15 36.01,101.14 35.84,101.03 35.74,100.86 35.74,100.84 35.42,100.53 35.39,100.49 35.37,100.45 35.22,100.45 35.11,100.4 35.07,100.29 35.07,99.69 34.7,99.32 34.63,99.22 34.61,99.1 34.61,98.64 34.51,98.54 34.51,97.66 34.14,97.29 33.93,97.29 33.81,97.4 33.81,99.46 33.61,99.67 32.92,99.67 31.81,100.78 31.81,101.53 31.78,101.67 31.69,101.8 31.49,102 31.49,103.98 31.52,104.06 31.54,104.15 31.54,104.37 31.55,104.38 31.55,105.75 32.6,106.8 33.14,106.8 33.26,106.83 33.36,106.89 34.14,107.66 35.47,107.66
TYPEC1_USB0 on BOTTOM (solid shape): 7.27,65.5 7.98,65.5 8,65.48 8,65.25 7.39,65.25 6.98,64.83 6.32,64.83 6.28,64.87 6.28,65.66 6.38,65.76 7.01,65.76
TYPEC1_USB0 on BOTTOM (solid shape): 7.22,68.68 7.22,68.17 7.37,68.02 7.4,68.02 7.4,68 8,68 8,67.74 7.4,67.74 7.4,67.71 7.34,67.71 7.12,67.48 6.3,67.48 6.24,67.55 6.24,67.7 6.23,67.71 6.23,68.68 6.35,68.81 7.09,68.81
TYPEC1_USB0 on BOTTOM (solid shape): 10.14,58.41 10.14,54.92 9.47,54.26 9.47,53.02 9.16,52.71 8.53,52.71 8.19,52.37 8.19,51.92 7.78,51.51 6.28,51.51 6.24,51.55 6.24,52.09 6.21,52.09 6.21,52.59 6.28,52.71 6.3,52.85 6.28,52.99 6.21,53.11 6.54,53.44 6.64,53.44 6.82,53.51 6.89,53.69 6.89,53.97 6.87,54.06 6.82,54.14 6.8,54.21 6.83,54.28 6.89,54.35 6.89,55.03 7.12,55.26 7.12,58.09 7.73,58.7 9.85,58.7
TYPEC1_USB0 on IN1 (solid shape): outline of 1500 points within 18.41,102.73 34.68,113.85
TYPEC1_USB0 on SVCC (solid shape): outline of 416 points within 2.53,52.09 22.15,111.01
TYPEC1_USB0 on IN2 (solid shape): outline of 628 points within 6.24,54.3 13.41,69.83
TYPEC1_USB0_PD on TOP (solid shape): 42.16,113.25 42.16,108.05 40.85,106.74 40.85,105.41 40.83,105.31 40.82,105.21 40.82,103.44 40.83,103.34 40.85,103.23 40.85,102.97 40.64,102.76 36.34,102.76 36.05,103.06 36.05,108.01 36.16,108.12 36.26,108.15 36.33,108.07 36.47,107.84 36.73,107.75 37.14,108.15 36.73,108.56 36.7,108.56 36.65,108.61 36.7,108.66 36.7,112.78 36.74,112.82 36.79,112.89 36.8,112.97 36.8,113.29 36.97,113.45 41.96,113.45
VA2 on TOP (solid shape): 73.31,200.28 73.31,196.95 72.98,196.62 71.99,196.62 69.81,194.44 69.78,194.45 69.72,194.46 69.66,194.47 69.48,194.42 69.34,194.31 69.22,194.31 69.07,194.42 68.9,194.46 68.82,194.45 68.74,194.43 68.71,194.41 68.51,194.61 68.51,197.61 68.71,197.81 69.57,197.81 69.88,198.12 69.88,200.28 70.08,200.48 73.1,200.48
VADPBL on TOP (solid shape): 69.24,205.97 69.24,205.46 69.21,205.43 68.47,205.43 68.13,205.08 68.13,201.37 67.8,201.04 66.92,201.04 66.81,201.02 66.72,200.96 66.68,200.91 57.74,200.91 57.43,201.22 57.43,205.91 57.59,206.07 69.14,206.07
N16821711 on BOTTOM (solid shape): 79.51,187.88 79.64,187.8 79.78,187.78 79.93,187.8 80.05,187.88 80.18,187.88 80.3,187.8 80.45,187.77 80.59,187.8 80.71,187.87 80.73,187.88 80.84,187.88 80.98,187.76 81.16,187.72 81.31,187.75 81.44,187.83 81.64,187.63 82.21,187.63 82.48,187.36 82.6,187.28 82.73,187.25 82.99,187.25 82.99,186.1 82.29,185.41 81.72,185.41 81.64,185.49 81.64,186.33 81.44,186.53 79.1,186.53 79.07,186.51 79.06,186.51 78.92,186.37 78.92,186.36 78.9,186.33 78.9,186.05 78.44,185.6 77.65,185.6 77.5,185.75 77.5,187.55 77.74,187.79 77.76,187.79 77.86,187.82 77.95,187.88
N17061293 on TOP (solid shape): 76.69,205.58 76.69,200.99 76.42,200.72 76.19,200.72 76.13,200.71 76.09,200.68 70.29,200.68 69.62,201.34 69.62,205.97 69.83,206.17 76.1,206.17
N17061319 on TOP (solid shape): 148.19,120.8 148.19,119.81 147.73,119.35 147.73,119.28 147.72,119.27 147.7,119.19 147.69,119.1 147.7,119.01 147.72,118.92 147.73,118.91 147.73,118.84 147.86,118.72 147.86,117.74 147.58,117.46 147.58,114.92 145.5,112.85 145.39,112.82 145.33,112.92 145.33,112.94 144.92,113.35 144.52,112.94 144.54,112.82 144.59,112.7 144.6,112.6 144.51,112.54 139.26,112.54 139.22,112.58 139.22,119.02 139.25,119.05 139.26,119.05 139.32,119.09 139.36,119.15 139.36,119.17 139.4,119.2 139.4,119.22 140.16,119.99 142.3,119.99 142.39,119.93 142.38,119.83 142.32,119.7 142.3,119.56 142.43,119.24 142.76,119.1 142.92,119.13 143.06,119.22 143.13,119.24 143.19,119.21 143.34,119.11 143.52,119.08 143.84,119.21 143.98,119.54 143.95,119.69 143.88,119.82 143.86,119.93 143.96,119.99 144.02,119.99 144.92,120.89 148.1,120.89
N17061319 on BOTTOM (solid shape): 142.12,119.39 142.12,113.86 141.63,113.38 139.6,113.38 138.94,114.04 138.94,117.07 139.29,117.41 139.29,118.46 139.69,118.85 139.69,119.6 139.88,119.8 141.71,119.8
N17072870 on TOP (solid shape): 166.65,166.83 167.03,166.83 167.11,166.83 167.11,166.7 166.47,166.06 166.47,162.05 166.11,161.69 166.11,161 165.94,160.82 165.05,160.82 163.57,162.3 163.57,165.98 164.22,166.63 166.36,166.63 166.58,166.84
N17072870 on BOTTOM (solid shape): 167.54,167.46 167.54,166.39 167.49,166.34 167.37,166.44 167.21,166.47 166.96,166.37 166.83,166.13 166.73,166.13 166.47,165.86 166.47,160.81 166.29,160.63 165.54,160.63 165.54,160.64 163.39,162.79 159.67,162.79 159.49,162.97 159.49,166.33 159.69,166.52 163.29,166.52 163.64,166.87 163.64,167.62 163.76,167.74 167.26,167.74
N17074882 on BOTTOM (solid shape): 92.31,194.84 92.63,194.67 92.96,194.83 96.78,194.83 97.27,194.33 97.59,194.33 97.79,194.13 97.79,193.47 97.46,193.14 96.9,193.14 96.85,193.15 96.8,193.15 96.58,193.09 96.43,192.91 95.25,192.91 95.05,192.71 95.05,191.13 94.95,191.03 93.68,191.03 93.57,191.14 93.57,192.55 93.88,192.86 93.88,193.21 93.63,193.47 93.07,193.47 92.78,193.18 92.12,193.18 91.85,192.91 91.85,192.45 91.8,192.4 90.12,192.4 90.12,192.96 89.52,193.57 89.21,193.57 89.08,193.7 89.08,194.71 89.21,194.84
N17074965 on TOP (solid shape): 38.26,136.83 38.25,136.8 38.24,136.77 38.24,136.74 38.24,136.36 38.27,136.27 38.34,136.21 38.37,136.2 38.37,135.42 38.26,135.31 37.51,135.31 37.28,135.07 37.28,134.09 37.57,133.79 38.49,133.79 38.61,133.66 38.61,132.4 38.52,132.31 34.76,132.31 34.47,132.59 34.47,135.23 33.92,135.78 33.92,136.73 34.06,136.87 38.22,136.87
N17419880 on TOP (solid shape): 35.8,103.57 35.8,103.01 36.23,102.58 36.78,102.58 37.04,102.32 37.04,101.87 36.82,101.65 35.19,101.65 35.13,101.71 35.13,102.3 34.98,102.46 33.45,102.46 33.2,102.7 33.2,103.76 33.69,104.25 35.12,104.25
N18723876 on TOP (solid shape): 25.84,190.96 25.84,186.41 27.41,184.85 38.45,184.85 38.67,184.62 38.67,183.51 38.31,183.14 25.76,183.14 23.62,185.28 23.62,190.82 23.83,191.03 25.78,191.03
N18723876 on BOTTOM (solid shape): 27.71,192.14 27.71,190.08 27.52,189.89 24.47,189.89 24.03,190.33 24.03,191.52 24.81,192.3 27.56,192.3
N18867651 on BOTTOM (solid shape): 203.81,129.97 204.05,129.97 204.11,129.94 204.17,129.94 204.47,129.94 204.53,129.94 204.6,129.97 205.79,129.97 206.08,129.68 207.39,129.68 207.77,130.05 208.75,130.05 208.89,129.92 208.89,128.39 208.78,128.28 206.18,128.28 205.8,128.65 205.67,128.74 205.52,128.77 205.5,128.77 205.47,128.81 203.9,128.81 203.77,128.88 203.64,128.9 203.5,128.88 203.37,128.81 203.13,128.81 202.47,129.47 202.4,129.52 202.32,129.54 202.25,129.54 202.16,129.62 201.36,129.62 201.31,129.68 201.31,129.83 201.99,129.83 201.99,130.02 201.31,130.02 201.31,130.23 201.41,130.33 203.45,130.33
N18867812 on TOP (solid shape): 33.66,162.74 33.68,162.73 33.88,162.73 33.88,161.99 34.08,161.99 34.08,162.73 34.28,162.73 34.28,161.99 34.3,161.99 34.3,161.79 34.3,161.78 34.27,161.73 34.26,161.67 34.26,161.45 33.91,161.1 33.91,159.54 33.85,159.42 33.83,159.29 33.85,159.17 33.9,159.06 33.91,159.05 33.91,158.88 33.88,158.83 33.56,158.51 32.43,158.51 32.33,158.62 32.36,158.66 32.37,158.72 32.37,160.09 32.36,160.15 32.33,160.2 32.33,161.21 32.19,161.34 32.19,161.36 32.15,161.45 32.08,161.53 31.68,161.93 31.66,161.95 31.66,162.63 31.78,162.74 33.63,162.74
N18922914 on TOP (solid shape): 125.11,199.8 125.15,199.79 125.18,199.8 125.23,199.8 125.88,199.8 125.93,199.8 125.99,199.79 126.25,199.54 126.25,199.29 126.13,199.17 125.99,199.17 125.85,199.03 125.85,198.47 125.96,198.36 125.96,198.24 126.65,198.24 126.68,198.2 126.68,197.79 126.44,197.55 125.61,197.55 125.51,197.44 124.81,197.44 124.7,197.34 123.08,197.34 122.94,197.48 122.94,198.04 123.14,198.24 124.15,198.24 124.25,198.19 124.36,198.17 124.59,198.26 124.69,198.5 124.65,198.64 124.56,198.76 124.56,199.64 124.72,199.8 125.06,199.8
N22317721 on TOP (solid shape): 33.99,45.66 33.99,45.13 34.08,45.04 35.19,45.04 35.24,44.98 35.24,44.34 35.19,44.29 34.14,44.29 33.8,43.95 33.09,43.95 32.97,44.07 32.97,45.48 33.24,45.75 33.9,45.75
N22317721 on BOTTOM (solid shape): 34.01,45.67 34.01,44.14 33.81,43.94 31.96,43.94 31.64,44.26 31.64,45.18 32.22,45.77 33.91,45.77
N22430755 on TOP (solid shape): 138.42,126.76 138.42,125.81 138.39,125.77 138.38,125.73 138.08,125.43 138.08,119.36 138.08,119.25 138.38,118.94 138.72,118.94 138.89,118.78 138.89,117.39 138.76,117.27 136.22,117.27 135.77,116.81 135.44,116.81 135.31,116.94 135.31,119 135.51,119.2 135.51,119.21 135.53,119.22 135.53,122.69 135.51,122.7 135.51,125.76 135.75,126 136.56,126 136.66,126.1 136.66,126.2 136.68,126.24 136.68,126.28 136.68,126.66 137,126.97 138.2,126.97
N22430755 on BOTTOM (solid shape): 139.31,119.02 138.95,118.67 138.95,117.65 138.82,117.52 135.49,117.52 135.32,117.68 135.32,121.32 135.61,121.62 139.31,121.62
N24359231 on BOTTOM (solid shape): 156.59,143 156.59,142.54 156.4,142.35 156.16,142.35 155.41,143.1 155.25,143.1 155.25,143.41 156.19,143.41
N24359390 on BOTTOM (solid shape): 157.61,143.71 157.61,142.97 157.52,142.88 156.94,142.88 156.21,143.61 155.25,143.61 155.25,143.91 156.19,143.91 156.19,143.91 157.41,143.91
N24507636 on BOTTOM (solid shape): 9.78,41.84 9.78,36.96 9.94,36.79 10.52,36.79 10.76,36.56 10.76,35.86 10.41,35.51 10.39,35.51 10.31,35.48 10.24,35.43 7.34,35.43 7.34,35.9 7.29,36.01 7.18,36.05 6.95,36.05 6.95,36.6 7,36.65 7.29,36.77 7.4,37.06 7.32,37.31 7.1,37.45 7.08,37.45 6.95,37.59 6.95,38.49 6.86,38.58 6.43,38.58 6.29,38.72 6.3,38.75 6.32,38.79 6.32,38.82 6.32,39.2 6.29,39.28 6.23,39.34 6.2,39.35 6.2,39.54 6.23,39.55 6.37,39.64 6.47,39.77 6.48,39.8 7.66,39.8 8.1,40.24 8.1,41.37 8.25,41.51 8.7,41.51 9.22,42.03 9.58,42.03
N24742107 on TOP (solid shape): 94.96,187.12 95.18,187.05 95.4,187.12 95.66,187.12 95.67,187.11 95.76,187.08 95.85,187.07 95.94,187.08 96.03,187.11 96.04,187.12 96.19,187.12 96.49,186.81 96.49,186.61 96.57,186.43 96.75,186.36 96.94,186.36 97.05,186.25 97.05,185.97 96.15,185.07 96.12,185.09 96.04,185.11 95.96,185.12 95.74,185.05 95.59,184.88 94.67,184.88 94.57,184.98 94.57,185.07 95.26,185.07 95.26,185.27 94.57,185.27 94.57,187.05 94.61,187.06 94.68,187.08 94.75,187.12
N24742107 on BOTTOM (solid shape): 96.22,185.89 97.48,185.89 97.74,185.62 97.74,184.81 97.61,184.68 96.5,184.68 96.35,184.83 96.35,184.84 96.2,185.04 95.96,185.12 95.88,185.11 95.81,185.09 95.78,185.08 95.41,185.45 95.41,186.17 95.51,186.27 95.84,186.27
N25430994 on TOP (solid shape): 18.45,148.1 18.45,147.31 17.63,146.49 16.89,146.49 15.84,145.44 14.15,145.44 13.57,146.02 13.57,146.68 13.8,146.92 16.56,146.92 17.8,148.16 18.39,148.16
N30442035 on TOP (solid shape): 35.88,161.99 36.08,161.99 36.08,162.73 37.9,162.73 38.07,162.57 38.07,161.59 37.95,161.47 37.95,159.41 37.81,159.27 36.16,159.27 36.04,159.39 36.04,160.92 35.94,161.02 35.94,161.04 35.88,161.14 35.79,161.2 35.75,161.22 35.75,161.61 35.74,161.69 35.69,161.76 35.61,161.85 35.61,161.9 35.64,161.99 35.68,161.99 35.68,162.73 35.88,162.73
N30568472 on BOTTOM (solid shape): 57.08,182.04 57.08,180.46 58.4,179.14 58.5,179.14 58.5,178.33 57.81,178.33 57.81,179.04 57.15,179.7 56.37,179.7 56.26,179.8 56.26,182.06 57.05,182.06
N31069510 on BOTTOM (solid shape): 203.21,127.76 203.28,127.71 203.36,127.69 204.57,127.69 205.26,127 205.26,125.63 205.11,125.48 204.19,125.48 203.71,125.95 202.67,125.95 202.33,126.29 201.88,126.29 201.29,126.88 201.29,127.83 201.99,127.83 201.99,128.02 201.29,128.02 201.29,128.19 201.32,128.23 201.99,128.23 201.99,128.24 202.73,128.24
N31353100 on TOP (solid shape): 34.74,140.85 34.74,138.99 34.6,138.86 33.55,138.86 33.48,138.92 33.48,140.89 33.61,141.02 34.57,141.02
N34044137 on BOTTOM (solid shape): 152.1,167.18 153.06,166.21 153.19,166.21 153.19,166.2 154.13,166.2 154.13,165.91 152.65,165.91 152.63,165.94 152.54,166.05 152.42,166.13 152.41,166.13 151.82,166.72 150.07,166.72 149.94,166.85 149.94,167.18 149.96,167.2 152.1,167.2
N34045547 on TOP (solid shape): 168.46,132.51 168.79,132.51 169.45,131.85 169.45,131.19 169.4,131.14 168.61,131.14 168.56,131.19 168.56,131.85 168.18,132.23 166.37,132.23 166.37,132.51 167.39,132.51 167.69,132.81 168.15,132.81
N34045574 on TOP (solid shape): 168.33,131.85 168.33,131.57 168.15,131.39 167.9,131.39 167.57,131.72 166.37,131.72 166.37,132 167.34,132 167.4,132.06 168.11,132.06
N34047656 on BOTTOM (solid shape): 155.68,159.1 155.68,158.31 155.5,158.14 154.99,158.14 154.84,158.29 154.84,158.29 154.69,158.45 154.69,159.18 155.6,159.18
N34047677 on BOTTOM (solid shape): 157.15,159.38 157.15,158.75 157.04,158.63 156.4,158.63 155.65,159.38 155.63,159.38 155.63,159.39 154.69,159.39 154.69,159.69 156.85,159.69
N45124268 on TOP (solid shape): 29.78,177.37 29.73,177.33 29.72,177.33 29.54,177.18 29.47,176.95 29.58,176.67 29.89,176.53 29.9,176.49 29.9,176.1 29.43,175.63 28.94,175.63 28.87,175.67 28.84,175.75 28.85,175.79 28.85,175.82 28.44,176.23 28.04,175.82 28.04,175.79 28.04,175.75 28.02,175.67 27.94,175.63 26.04,175.63 26.02,175.66 26.02,177.37 26.08,177.44 29.72,177.44
N45124292 on TOP (solid shape): 28.36,175.42 28.44,175.42 28.52,175.42 28.61,175.45 31.25,175.45 31.68,175.02 31.68,174.55 31.59,174.46 31.1,174.46 30.75,174.8 30.39,174.8 30.36,174.81 29.8,174.81 29.77,174.8 29.54,174.8 28.94,174.2 28.94,173.71 28.46,173.24 26.91,173.24 26.8,173.34 26.8,175.31 26.94,175.45 28.28,175.45
N45124296 on TOP (solid shape): 34.37,175.97 34.45,175.89 34.45,175.49 34.41,175.45 32.99,175.45 32.84,175.3 32.84,174.34 31.94,173.45 31.48,173.45 31.37,173.56 31.37,173.92 31.94,174.49 31.94,175.89 32.02,175.97 33.46,175.97
N45366087 on BOTTOM (solid shape): 200.2,126.03 200.41,126.03 200.45,125.99 200.83,125.99 200.87,125.98 200.9,125.98 201.31,125.98 201.65,125.64 201.65,125.63 201.7,125.55 201.78,125.5 201.79,125.5 202.91,124.38 202.96,124.38 202.99,124.35 202.99,123.6 202.92,123.54 202.25,123.54 202.21,123.58 202.21,123.61 202.22,123.67 202.23,123.72 202.22,123.81 202.19,123.89 202.19,123.9 202.19,124.36 201.43,125.11 201.43,125.12 201.37,125.19 201.29,125.22 200.9,125.22 200.86,125.21 200.81,125.18 200.75,125.18 200.28,125.65 198.81,125.65 198.77,125.69 198.77,125.99 198.82,126.04 200.19,126.04
N47271970 on BOTTOM (solid shape): 122.2,178.18 122.2,177.5 122.43,177.27 122.43,176.65 122.39,176.61 121.03,176.61 119.84,177.8 118.87,177.8 118.77,177.9 118.77,178.3 122.07,178.3

Small or netless copper shapes (teardrops, artwork), in the pictures only: 106 on TOP, 21 on BOTTOM, 18 on IN2, 2 on IN4

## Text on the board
Ref Des/Silkscreen Bottom: Please do not print out the lines with 0.39mils/0.01mm in width | MODEL:Z8I | Acer Incorp. | DA0Z8IMBAC0 REV:C
User.Comments: 16x35 | 30x32 | 33x37 | 87x106
Ref Des/Silkscreen Top: DA0Z8IMBAC0 REV:C | Please do not print out the lines with 0.39mils/0.01mm in width | Acer Incorp.
PAGE_OUTLINE: pcba align holes | Connector align holes | .
User.6: SD | EC | GMR SENSOR | Hall sensor
User.7: USB3 | RJ45 | HDMI | D-sub | TYPEC | DC-IN | SSD | Audio | IR CCD | P2 speaker conn | 14" KB | FAN | 15" KB | LTE SUB-PCB | (LTE/SIM CARD) | RTC battery | Stylus cable | Viki speaker | EDP | NFC | TP FINGER | GMR SENSOR PCB | TP | BATTERY | WIFI | P2/USB2 | SPIN side key | (Volume btn *2/FP/PWR-BTN/LED*2) | SMART card | BACK-LIGHT | Viki RS232-2LED | HDD
User.8: SD | GMR SENSOR | Hall sensor | EC
User.9: USB3 | RJ45 | HDMI | D-sub | TYPEC | DC-IN | SSD | Audio | IR CCD | Stylus cable | Viki speaker | RTC battery | EDP | NFC | TP FINGER | GMR SENSOR PCB | P2 speaker conn | BATTERY | TP | 14" KB | FAN | 15" KB | P2/USB2 | SPIN side key | (Volume btn *2/FP/PWR-BTN/LED*2) | WIFI | LTE SUB-PCB | (LTE/SIM CARD) | SMART card | BACK-LIGHT | HDD | Viki RS232-2LED
User.12: VCCPRIM_1P8 | ADOGND | TYPEC1_USB0 | +5VPCU | +1.05V_DEEP_SUS | +VAC_IN | +1.8V_S5 | GND | +5V_S5 | +5V | +1V8_GFX_MAIN | +1V8_AON | +VCC_CORE | +VGPU_CORE | +VCCGT | +VCCSA | +3V
User.26: pcba align holes | Connector align holes | .
User.32: A-9
User.33: ADOGND | GND
User.34: GND | ADOGND
User.35: ADOGND | GND
User.43: Z8I-MB | DATE | 08/26/19' | PROJECT | LAYER | REV. | B | 10 | BOTTOM | DA0Z8IMBAB0 | 17.2
User.44: Z8I-MB | DATE | 08/26/19' | PROJECT | LAYER | REV. | IN1 | B | 3 | DA0Z8IMBAB0 | 17.2
User.45: Excess check:Jul 12 10:14:31 2019 | No Route Under Component:Jul 12 10:34:17 2019 | PadStack_Check:Jul 12 10:05:37 2019 | TP check:Jul 12 10:05:44 2019 | XY-Check acute:Jul 12 10:20:48 2019 | XY-Create nettxt:Jul 09 16:31:07 2019 | XY-Create plane:Jul 12 09:49:40 2019 | XY-Cross plane-BOTTOM-SGND2:Jul 12 10:29:36 2019 | XY-Cross plane-IN1-SGND:Jul 12 10:29:09 2019 | XY-Cross plane-IN1-SVCC:Jul 12 10:29:05 2019 | XY-Cross plane-IN2-SVCC:Jul 12 10:29:13 2019 | XY-Cross plane-IN3-SGND1:Jul 12 10:29:18 2019 | XY-Cross plane-IN4-SGND1:Jul 12 10:29:30 2019 | XY-Cross plane-IN4-SGND2:Jul 12 10:29:24 2019 | XY-Cross plane-TOP-SGND:Jul 12 10:29:01 2019 | XY-Dxf to pin check:Jul 12 10:11:34 2019 | XY-Etch cross-IN2-IN3:Jul 12 10:29:12 2019 | XY-Etch ref-BOTTOM-SGND2:Jul 12 10:29:47 2019 | XY-Etch ref-IN1-SGND:Jul 12 10:29:12 2019 | XY-Etch ref-IN1-SVCC:Jul 12 10:29:09 2019 | XY-Etch ref-IN2-SVCC:Jul 12 10:29:18 2019 | XY-Etch ref-IN3-SGND1:Jul 12 10:29:23 2019 | XY-Etch ref-IN4-SGND1:Jul 12 10:29:36 2019 | XY-Etch ref-IN4-SGND2:Jul 12 10:29:30 2019 | XY-Etch ref-TOP-SGND:Jul 12 10:29:05 2019 | XY-Excess check:Jul 12 10:14:31 2019 | XY-NO Route Under Component:Jul 12 10:34:17 2019 | XY-Outline check:Jul 12 10:34:23 2019 | XY-PadStack_Check:Jul 12 10:05:37 2019 | XY-Plane net check:Jul 12 10:12:49 2019 | XY-Prop check:Jul 12 10:28:38 2019 | XY-TP check:Jul 12 10:05:44 2019 | XY-shape min check:Jul 12 10:03:21 2019 | XY-via check:Jul 12 10:31:33 2019 | check acute:Jul 12 10:20:48 2019 | cross plane-BOTTOM-SGND2:Jul 12 10:29:36 2019 | cross plane-IN1-SGND:Jul 12 10:29:09 2019 | cross plane-IN1-SVCC:Jul 12 10:29:05 2019 | cross plane-IN2-SVCC:Jul 12 10:29:13 2019 | cross plane-IN3-SGND1:Jul 12 10:29:18 2019 | cross plane-IN4-SGND1:Jul 12 10:29:30 2019 | cross plane-IN4-SGND2:Jul 12 10:29:24 2019 | cross plane-TOP-SGND:Jul 12 10:29:01 2019 | dxf to pin check:Jul 12 10:11:34 2019 | etch cross-IN2-IN3:Jul 12 10:29:12 2019 | etch ref-BOTTOM-SGND2:Jul 12 10:29:47 2019 | etch ref-IN1-SGND:Jul 12 10:29:12 2019 | etch ref-IN1-SVCC:Jul 12 10:29:09 2019 | etch ref-IN2-SVCC:Jul 12 10:29:18 2019 | etch ref-IN3-SGND1:Jul 12 10:29:23 2019 | etch ref-IN4-SGND1:Jul 12 10:29:36 2019 | etch ref-IN4-SGND2:Jul 12 10:29:30 2019 | etch ref-TOP-SGND:Jul 12 10:29:05 2019 | outline check:Jul 12 10:34:23 2019 | plane net check:Jul 12 10:12:49 2019 | prop check:Jul 12 10:28:38 2019 | shape min check:Jul 12 10:03:21 2019 | via check:Jul 12 10:31:33 2019 | Z8I-MB | DATE | 08/26/19' | PROJECT | LAYER | REV. | IN2 | IN3 | IN4 | TOP | B | 1 | 5 | 6 | 8 | FIGURE | TYPE | Circle | Oblong | Rectangle | SIZE | 10.0 | 12.0 | 14.0 | 18.0 | 22.0 | 28.0 | 32.0 | 35.0 | 118.0 | 126.0 | 146.0 | 177.0 | 240.0 | 33.0 | 37.0 | 38.0 | 41.0 | 43.0 | 45.0 | 47.0 | 63.0 | 67.0 | 87.0 | 43.0x20.0 | 49.0x20.0 | 59.0x20.0 | 59.0x28.0 | 63.0x31.0 | 71.0x31.0 | 75.0x39.0 | 91.0x28.0 | 98.0x24.0 | 102.0x31.0 | 118.0x20.0 | 157.0x157.0 | DRILL CHART: TOP to BOTTOM | ALL UNITS ARE IN MILS | PLATED | NON-PLATED | ROTATION | - | 90.000 | 0.000 | QTY | 6426 | 25 | 345 | 10 | 19 | 15 | 18 | 3 | 2 | 6906 | 4 | 41 | TOTAL HOLES: | DA0Z8IMBAB0 | 17.2
